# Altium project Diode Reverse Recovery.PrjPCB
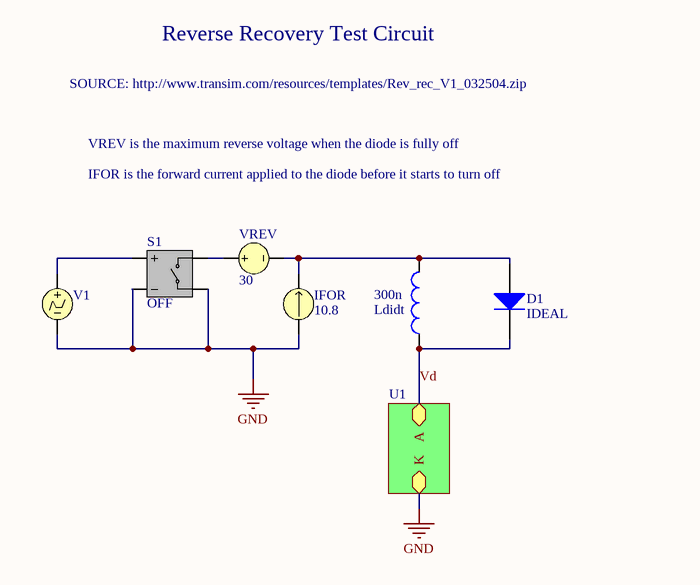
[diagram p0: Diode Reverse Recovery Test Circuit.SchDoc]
2 sheets, 15 parts. Net scope: hierarchical (ports join the sheet entries above them; power ports are global).
Sheets:
  Diode Reverse Recovery Test Circuit.SchDoc
    U1 = Diode Model.SchDoc

## Sheet Diode Reverse Recovery Test Circuit.SchDoc
size A4

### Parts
D1  IDEAL  [SMC]
IFOR  10.8
Ldidt  value 300n  [0402-A]  (hidden comment: Inductor)
S1  Initial Condition: OFF  (hidden comment: VSW)
V1  VPWL  (value not drawn)
VREV  30

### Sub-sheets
U1 = Diode Model: K, A

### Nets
GND: IFOR.1 S1.2(N1-) S1.4(N2-) V1.2 ; sheet U1/K
Vd: D1.2(K) Ldidt.1 ; sheet U1/A
NetD1_1: D1.1(A) IFOR.2 Ldidt.2 VREV.2
NetS1_1: S1.1(N1+) V1.1
NetS1_3: S1.3(N2+) VREV.1

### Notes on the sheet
- SOURCE: http://www.transim.com/resources/templates/Rev_rec_V1_032504.zip
- Reverse Recovery Test Circuit
- VREV is the maximum reverse voltage when the diode is fully off
- IFOR is the forward current applied to the diode before it starts to turn off

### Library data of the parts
D1 = Diode: Default Diode
IFOR = ISRC: Current Source; Note: PCB Footprint - Not required
Ldidt = Inductor: Code_IEC: 1005
S1 = VSW: Voltage Controlled Switch
V1 = VPWL: Piecewise Linear Voltage Source; Note: PCB Footprint - Not required; Sim Note: To add model file containing time-current pairs of values, enter model location under "General Tab" in "Full Path" box.; Time-Value Pairs: 0 0 50n 5 1 5
VREV = VSRC: Voltage Source; Note: PCB Footprint - Not required

## Sheet Diode Model.SchDoc
size A4
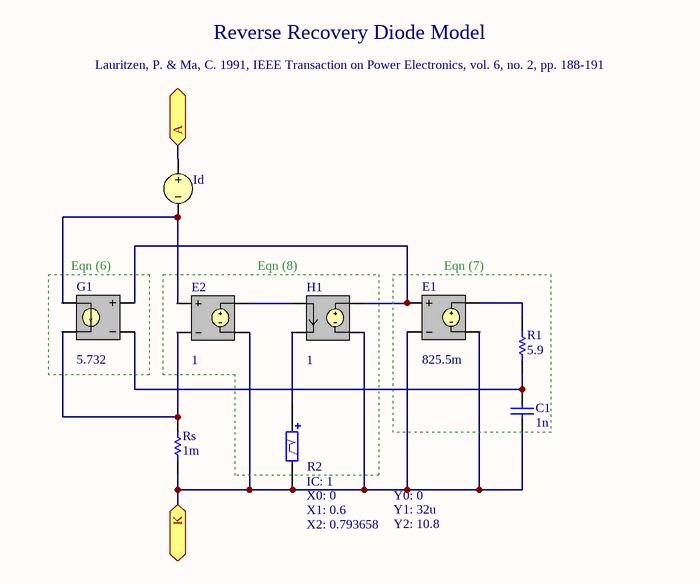
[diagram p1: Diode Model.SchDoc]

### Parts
C1  value 1n  [RAD-0.3]  (hidden comment: Cap)
E1  825.5m
E2  1
G1  5.732
H1  1
Id  VSRC  (value not drawn)
R1  value 5.9  [AXIAL-0.3]  (hidden comment: Res1)
R2  IC: 1  X0: 0  X1: 0.6  Y1: 32u  X2: 0.793658  Y2: 10.8  (hidden comment: SIMPLIS VPWLR2)
Rs  value 1m  [AXIAL-0.3]  (hidden comment: Res1)

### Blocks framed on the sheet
Eqn (6): G1
Eqn (8): E2 H1 R2
Eqn (7): C1 E1 R1

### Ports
A, K

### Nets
GND: C1.1 E1.2(NC-) E1.4(N-) E2.4(N-) H1.4(N-) R2.2 Rs.1 ; port K
Vd: Id.1 ; port A
NetC1_2: C1.2 G1.2(NC-) R1.1
NetE1_1: E1.1(NC+) G1.1(NC+) H1.3(N+)
NetE1_3: E1.3(N+) R1.2
NetE2_1: E2.1(NC+) G1.3(N+) Id.2
NetE2_2: E2.2(NC-) G1.4(N-) Rs.2
NetE2_3: E2.3(N+) H1.1(NC+)
NetH1_2: H1.2(NC-) R2.1

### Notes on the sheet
- Reverse Recovery Diode Model
- Lauritzen, P. & Ma, C. 1991, IEEE Transaction on Power Electronics, vol. 6, no. 2, pp. 188-191

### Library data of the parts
C1 = Cap: Capacitor
E1 E2 = ESRC: Voltage Controlled Voltage Source; Note: PCB Footprint - Not required; Sim Note: Enter gain into gain field
G1 = GSRC: Voltage Controlled Current Source; Note: PCB Footprint - Not required; Sim Note: Enter gain into GAIN field
H1 = HSRC: Current Controlled Voltage Source; Note: PCB Footprint - Not required; Sim Note: Enter gain into gain field
Id = VSRC: Voltage Source; Note: PCB Footprint - Not required; Value: 0
R1 Rs = Res1: Resistor
R2 = SIMPLIS VPWLR2: Voltage-Controlled Piecewise Linear Resistor (2-segment)

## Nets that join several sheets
GND: Diode Reverse Recovery Test Circuit (IFOR.1 S1.2 S1.4 V1.2), Diode Model (7 pins)
Vd: Diode Reverse Recovery Test Circuit (D1.2 Ldidt.1), Diode Model (Id.1)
